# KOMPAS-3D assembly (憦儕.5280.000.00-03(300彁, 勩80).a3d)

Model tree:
1. Плоскость XY
2. Плоскость ZX
3. Плоскость ZY
4. Ось X
5. Ось Y
6. Ось Z
7. Начало координат  (labels: Операция без истории:1; ␣0; ␣3␣ĳ; ␣5)

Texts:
  Линия-выноска #1
  Линия-выноска #2
  Линия-выноска #3
  Отклонения формы и база
  Марка координационной оси
  Марка/позиционное обозначение с линией-выноской
  Марка/позиционное обозначение на линии
  Марка/позиционное обозначение без линии-выноски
